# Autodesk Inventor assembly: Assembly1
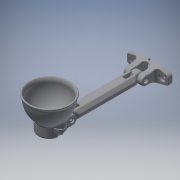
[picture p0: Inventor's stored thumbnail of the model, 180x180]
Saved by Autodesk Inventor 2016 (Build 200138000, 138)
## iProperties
Created: 2015-05
Part Number: Assembly1
Document SubType Name: Assembly
Designer: Brent
Author: Brent
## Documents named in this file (6)
- G:\Projects\Flashlight Floodlight\Assembly1.iam
- G:\Projects\Flashlight Floodlight\leds.ipt
- G:\Projects\Flashlight Floodlight\shroud.ipt
- G:\Projects\Flashlight Floodlight\fixture.ipt
- G:\Projects\Flashlight Floodlight\armchannel.ipt
- G:\Projects\Flashlight Floodlight\mount.ipt
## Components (5 placed, 5 different names)
1. leds:1 — Flush:1
2. shroud:1 — Flush:1, Flush:2
3. fixture:1 — Flush:2, Flush:3
4. armchannel:1 — Flush:3, Flush:4, Flush:5
5. mount:1 — Flush:4, Flush:5
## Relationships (5: Flush 5)
- Flush:1: leds:1 ↔ shroud:1
- Flush:2: shroud:1 ↔ fixture:1
- Flush:3: fixture:1 ↔ armchannel:1
- Flush:4: armchannel:1 ↔ mount:1
- Flush:5: armchannel:1 ↔ mount:1
